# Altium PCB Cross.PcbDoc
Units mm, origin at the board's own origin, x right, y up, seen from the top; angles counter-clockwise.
Board outline 100 x 65 mm, 2 copper layers (Top Layer, Bottom Layer); 31 components, 20 nets, 115 pads, 5 vias.
Unrouted connection lines stored in the file: 4.
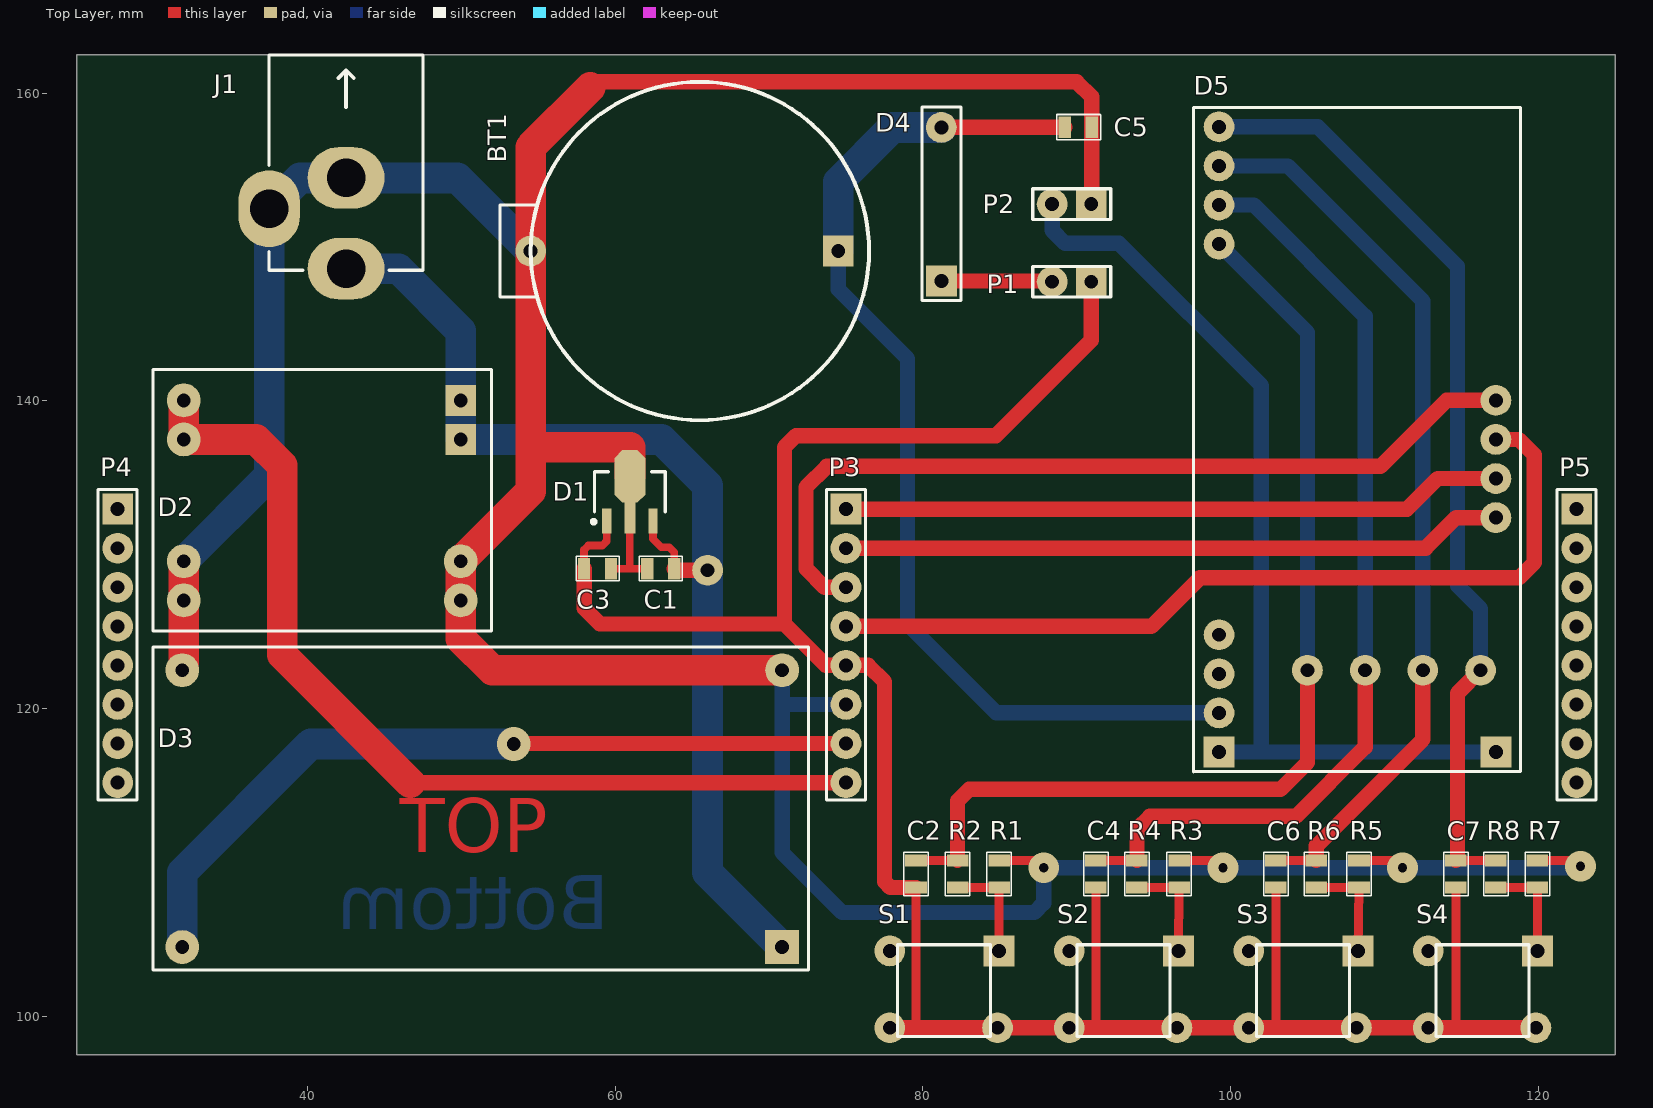
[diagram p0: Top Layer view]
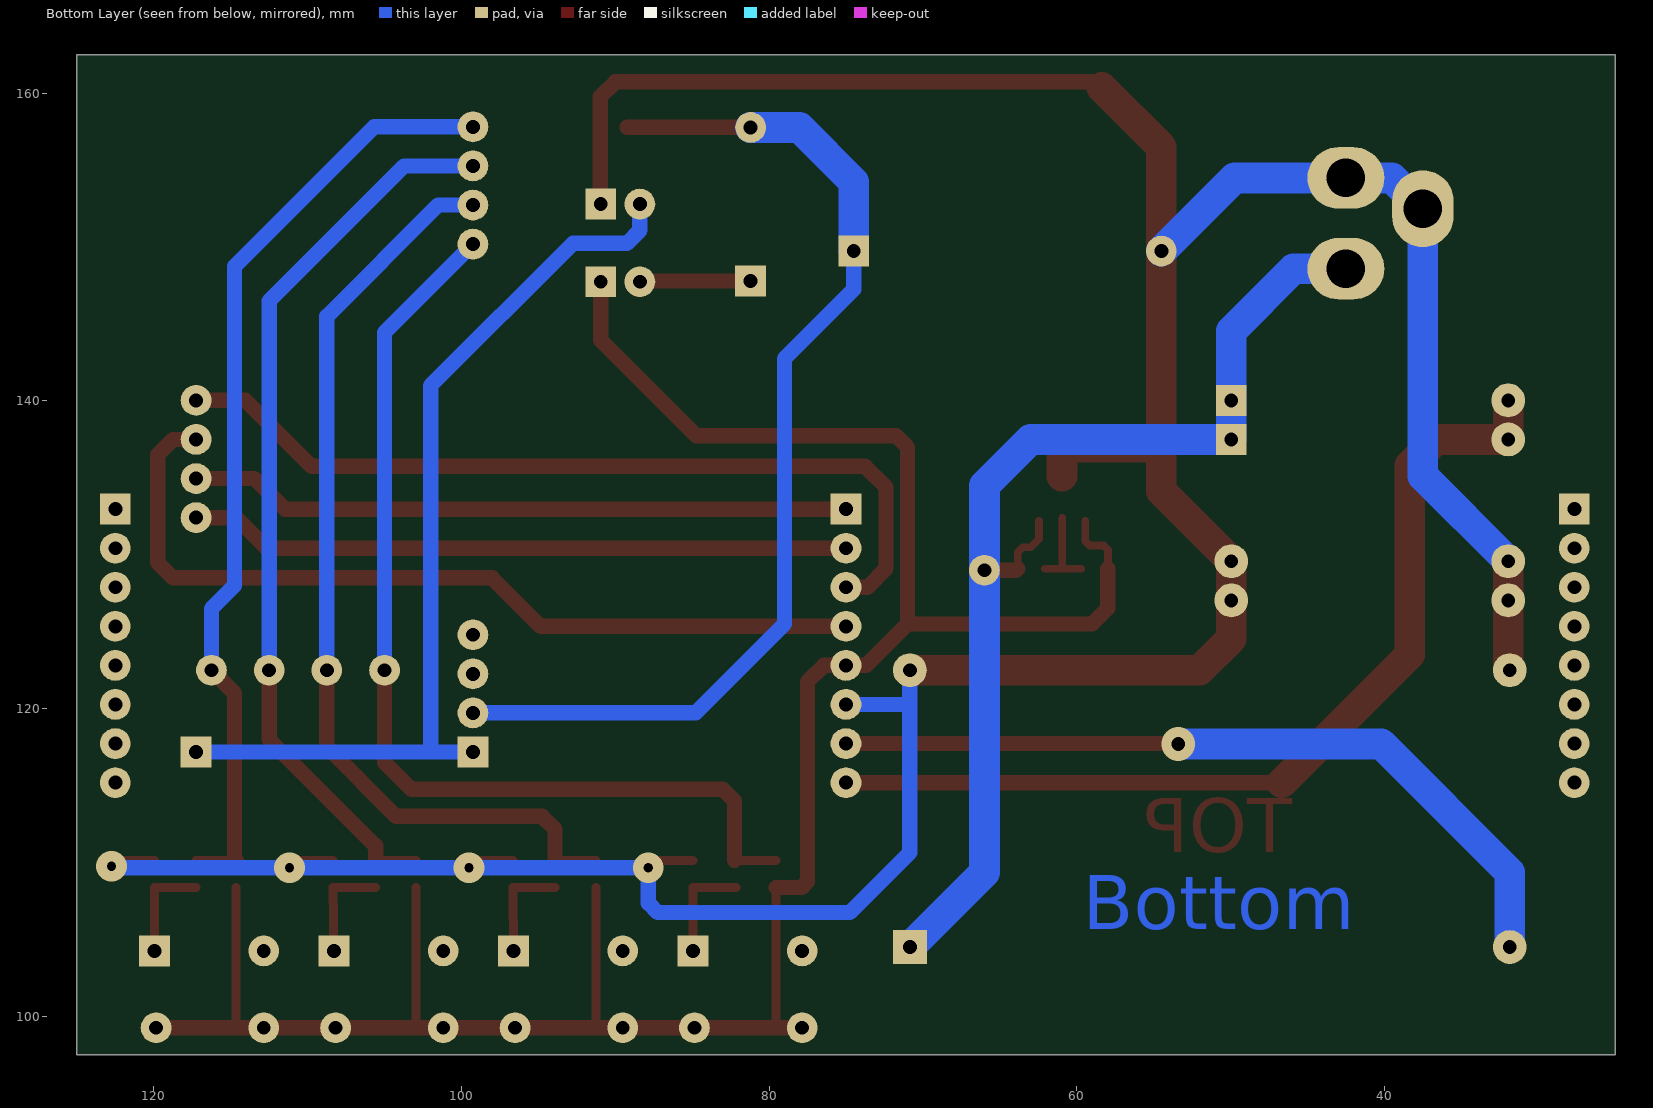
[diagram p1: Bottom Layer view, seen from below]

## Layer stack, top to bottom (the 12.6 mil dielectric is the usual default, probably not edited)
Top Solder: solder mask 0.0102, Solder Resist, Dk 3.5
Top Layer: signal copper 0.0356
Dielectric 1: dielectric 0.32, FR-4, Dk 4.8
Bottom Layer: signal copper 0.0356
Bottom Solder: solder mask 0.0102, Solder Resist, Dk 3.5

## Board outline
25,97.5 25,162.5 125,162.5 125,97.5

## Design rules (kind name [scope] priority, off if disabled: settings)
Clearance [All] p1: gap=0.4 ignorepadtopadclearanceinfootprint=FALSE except(0: Arc-Hole Track-Hole SMDPad-Hole THPad-Hole Via-Hole Fill-Hole Poly-Hole Region-Hole Text-Hole)
PolygonConnect [All] p1: connectstyle=Relief reliefconductorwidth=0.254 reliefentries=4 polygonreliefangle="90 Angle" airgapwidth=0.254
RoutingVias [All] p1: holewidth=0.711 width=1.27 viastyle="Through Hole" minholewidth=0.711 minwidth=1.27 maxholewidth=0.711 maxwidth=1.27
SolderMaskExpansion [All] p1: expansion=0.102
Width [All] p1: maxlimit=2 minlimit=0.2 preferedwidth=1 minimp=50.000000 maximp=50.000000 favimp=50.000000
30 further rules are at their usual default settings.

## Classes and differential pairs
component class Cross: BT1 C1 C2 C3 C4 C5 C6 C7 D1 D2 D3 D4 D5 J1 P1 P2 P3 R1 R2 R3 R4 R5 R6 R7 R8 S1 S2 S3 S4

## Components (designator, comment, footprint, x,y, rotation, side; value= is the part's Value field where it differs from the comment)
BT1 "Battery" VBAT 74.5,149.75 r180 top
C1 "Capacitor" C0805 62.95,129.1 r0 top
C2 "Capacitor" C0805 79.55,109.25 r270 top
C3 "Capacitor" C0805 58.85,129.1 r180 top
C4 "Capacitor" C0805 91.25,109.25 r270 top
C5 "Capacitor" C0805 90.1,157.8 r180 top
C6 "Capacitor" C0805 102.95,109.25 r270 top
C7 "Capacitor" C0805 114.65,109.25 r270 top
D1 "78L03" SOT89M 60.95,134.1 r90 top
D2 "DC-DC_1.5V" DC-DC_1.5V 29.95,140.04 r0 top
D3 "DC-DC_30V" DC-DC_30V 71.85,104.5 r180 top
D4 "Diode 1N914" Diode 81.2,147.8 r90 top
D5 "STM32F103C8T6" STM32F103C8T6_13pins 99.25,117.18 r90 top
J1 "PWR2.5" KLD-0202 42.5,162.5 r270 top
P1 "Header 2" 2pin 90.94,147.75 r180 top
P2 "Header 2" 2pin 90.94,152.8 r180 top
P3 "8pin" 8PIN 75,132.97 r270 top
P4 "8pin" 8PIN 27.65,132.97 r270 top (schematic designator P3)
P5 "8pin" 8PIN 122.5,132.97 r270 top (schematic designator P3)
R1 "Rezistor" C0805 84.95,109.25 r270 top
R2 "Rezistor" C0805 82.25,109.25 r90 top
R3 "Rezistor" C0805 96.65,109.25 r270 top
R4 "Rezistor" C0805 93.917,109.25 r90 top
R5 "Rezistor" C0805 108.35,109.25 r270 top
R6 "Rezistor" C0805 105.583,109.25 r90 top
R7 "Rezistor" C0805 119.95,109.25 r270 top
R8 "Rezistor" C0805 117.25,109.25 r90 top
S1 "SW-DPST" DPST-4 81.85,100.25 r270 top
S2 "SW-DPST" DPST-4 93.517,100.25 r270 top
S3 "SW-DPST" DPST-4 105.183,100.25 r270 top
S4 "SW-DPST" DPST-4 116.85,100.25 r270 top

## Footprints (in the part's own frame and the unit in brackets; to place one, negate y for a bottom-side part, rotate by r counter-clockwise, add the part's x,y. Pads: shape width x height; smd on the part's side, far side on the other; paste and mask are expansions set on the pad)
2pin [mm] "Connector; Header; 4 Position"
  rect 2x2 hole 0.9: 1(0,0)
  round 2 hole 0.9: 2(2.54,0)
  silkscreen extent -1.27,-1 3.8,1
8PIN [mm] "Connector; Header; 4 Position"
  rect 2x2 hole 0.9: 1(0,0)
  round 2 hole 0.9: 2(2.54,0) 3(5.08,0) 4(7.62,0) 5(10.16,0) 6(12.7,0) 7(15.24,0) 8(17.78,0)
  silkscreen extent -1.27,-1.27 18.9,1.27
C0805 [mm] "Chip Capacitor, Body 2.0x1.3mm, IPC High Density"
  rect 0.8x1.4 smd: 1(-0.877,0) 2(0.877,0)
  silkscreen extent -1.4,-0.8 1.4,0.8, body extent -1.1,-0.72 1.1,0.72, height 1.4
DC-DC_1.5V [mm] "Connector; Header; 2 Position"
  rect 2x2 hole 0.9: 1(20,-2.54) 1(20,0)
  round 2.2 hole 0.9: 2(2,-2.54) 2(2,0) 3(2,-13) 3(2,-10.46) 4(20,-13) 4(20,-10.46)
  silkscreen extent 0,-15 22,2
DC-DC_30V [mm] "Connector; Header; 17 Position"
  rect 2.2x2.2 hole 0.9: 1(1,0)
  round 2.2 hole 0.9: 2(40,0) 3(1,-18) 4(40,-18)
  silkscreen extent -0.7,-19.5 41.9,1.5
Diode [mm] "Connector; Header; 4 Position"
  rect 2x2 hole 0.9: 1(0,0)
  round 2 hole 0.9: 2(9.98,0)
  silkscreen extent -1.27,-1.27 11.3,1.27
DPST-4 [mm] "Switch; 4 Leads"
  rect 2x2 hole 0.9: 1(-4,3.1)
  round 2 hole 0.9: 2(1,3) 3(-4,-4) 4(1,-4)
  silkscreen extent -4.4,-3.5 1.56,2.54
KLD-0202 [mm] "DC Power Jack, 2.5mm, KLD Series, PCB Mount"
  oval 4x5 hole 2.5: 1(13.9,0) 3(8,0)
  oval 5x4 hole 2.5: 2(10,-5)
  silkscreen extent 0,-5 14,5
SOT89M [mm] "SOT89, 3-Leads, Body 4.5x2.4 mm, Pitch 1.5mm, Lead Span 4.1mm, IPC Low Density"
  rect 1.6x0.6 smd: 1(-1.9,1.5) 3(-1.9,-1.5)
  rect 2x0.7 smd: 2(-1.7,0)
  oct 3.4x2 smd: 2(1,0)
  silkscreen extent -2.07,-2.3 1.3,2.47, body extent -1.3,-2.3 1.3,2.3, height 1.6
STM32F103C8T6_13pins [mm] "Connector; Header; 17 Position"
  rect 2x2 hole 0.9: 1(0,0) 18(0,-18)
  round 2 hole 0.9: 2(2.54,0) 3(5.08,0) 4(7.62,0) 14(33.02,0) 15(35.56,0) 16(38.1,0) 17(40.64,0) 24(15.24,-18) 25(17.78,-18) 26(20.32,-18) 27(22.86,-18)
  silkscreen extent -1.3,-19.6 41.91,1.67
VBAT [mm] "Connector; Header; 4 Position"
  rect 2x2 hole 0.9: 1(0,0)
  round 2 hole 0.9: 2(20,0)
  silkscreen extent -2,-11 22,11

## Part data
BT1: "Multicell Battery"
D4: "High Conductance Fast Diode"
J1: "Low Voltage Power Supply Connector"
P1 P2: "Header, 2-Pin"
S1 S2 S3 S4: "Double-Pole, Single-Throw Switch"

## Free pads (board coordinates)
  round 2 hole 0.9: 5(66,129) 5(105,122.5) 5(108.75,122.5) 5(112.5,122.5) 5(116.25,122.5)

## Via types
v1: diameter 2, hole 0.6, Top Layer to Bottom Layer, 4 vias
v2: diameter 2.2, hole 0.9, Top Layer to Bottom Layer, 1 vias

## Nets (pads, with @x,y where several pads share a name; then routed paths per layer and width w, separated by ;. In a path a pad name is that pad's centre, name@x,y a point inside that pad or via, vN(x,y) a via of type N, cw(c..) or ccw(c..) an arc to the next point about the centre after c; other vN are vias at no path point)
3V3: C2.2 C3.2 C4.2 C6.2 C7.2 D1.1 P1.1 P3.5 S1.2 S1.4 S2.2 S2.4 S3.2 S3.4 S4.2 S4.4 | length 160.3
  Top Layer w0.5: C3.2 57.973,130.323 58.25,130.6 59.15,130.6 59.45,130.9 D1.1
  Top Layer w0.6: 79.45,99.25 79.55,99.35 C2.2 ; 91.05,99.25 91.25,99.45 C4.2 ; 102.95,99.25 C6.2 ; 114.65,99.25 C7.2
  Top Layer w1: C3.2 57.973,126.527 59,125.5 71,125.5 ; S1.4 79.45,99.25 S1.2 S2.4 91.05,99.25 S2.2 S3.4 102.95,99.25 S3.2 S4.4 114.65,99.25 S4.2 ; C2.2 77.877,108.373 77.5,108.75 77.5,121.75 76.44,122.81 P3.5 73.69,122.81 71,125.5 ; P1.1 90.94,143.94 84.75,137.75 71.75,137.75 71,137 71,125.5
30V: D3.2 P3.7 | length 51.5
  Top Layer w1: v2(53.4,117.7) 53.43,117.73 P3.7
  Bottom Layer w2: D3.2 31.85,109.35 40.2,117.7 v2(53.4,117.7)
Button1: C2.1 D5.14 pad.5@105,122.5 R2.2 | length 66.4
  Top Layer w0.6: C2.1 R2.2
  Top Layer w1: R2.2 82.25,114 83,114.75 103.25,114.75 105,116.5 pad.5@105,122.5
  Bottom Layer w1: D5.14 105,144.45 pad.5@105,122.5
Button2: C4.1 D5.15 pad.5@108.75,122.5 R4.2 | length 62.2
  Top Layer w0.6: C4.1 R4.2
  Top Layer w1: R4.2 93.917,112.167 94.75,113 104.25,113 108.75,117.5 pad.5@108.75,122.5
  Bottom Layer w1: D5.15 101.51,152.74 108.75,145.5 pad.5@108.75,122.5
Button3: C6.1 D5.16 pad.5@112.5,122.5 R6.2 | length 58.8
  Top Layer w0.6: C6.1 R6.2
  Top Layer w1: R6.2 105.583,111.083 112.5,118 pad.5@112.5,122.5
  Bottom Layer w1: D5.16 103.72,155.28 112.5,146.5 pad.5@112.5,122.5
Button4: C7.1 D5.17 pad.5@116.25,122.5 R8.2 | length 61.8
  Top Layer w0.6: C7.1 R8.2
  Top Layer w1: C7.1 114.75,110.227 114.75,121 pad.5@116.25,122.5
  Bottom Layer w1: D5.17 105.68,157.82 114.75,148.75 114.75,128 116.25,126.5 pad.5@116.25,122.5
CLK: D5.24 P3.2 | length 43.1
  Top Layer w1: P3.2 112.68,130.43 114.67,132.42 D5.24
DS: D5.25 P3.1 | length 43.1
  Top Layer w1: P3.1 111.47,132.97 113.46,134.96 D5.25
Glow1: D2.2 P3.8 | length 62
  Top Layer w1: 46.675,115.175 46.69,115.19 P3.8
  Top Layer w2: D2.2@31.95,140.04 31.95,137.5 36.65,137.5 38.35,135.8 38.35,123.5 46.675,115.175
GND: BT1.2 C1.1 C3.1 C5.1 D1.2 D2.3 D2.4 D3.3 D3.4 J1.2 J1.3 P2.1 P3.6 R1.1 R3.1 R5.1 R7.1 | length 251.3
  Top Layer w0.5: C3.1 60.95,129.1 ; D1.2@60.95,132.4 60.95,129.1 ; C1.1 60.95,129.1 ; v1@122.373,110.127 v1(122.75,109.75)
  Top Layer w0.6: R1.1 87.373,110.127 v1(87.85,109.65) ; R3.1 99.04,110.127 v1(99.517,109.65) ; R5.1 110.706,110.127 v1(111.183,109.65) ; R7.1 v1@122.373,110.127
  Top Layer w1: 58.375,160.375 58.75,160.75 90,160.75 90.977,159.773 C5.1 90.977,152.987 P2.1@90.79,152.8
  Top Layer w2: D3.4@31.95,123 31.95,127.04 D2.3@31.95,129.58 ; 58.375,160.375 54.5,156.5 BT1.2 54.5,136.9 ; D1.2@60.95,135.1 60.95,137 54.6,137 54.5,136.9 ; D3.3 52,122.5 49.95,124.55 49.95,127.04 49.95,129.58 54.5,134.13 54.5,136.9
  Bottom Layer w1: D3.3 70.85,120 ; P3.6 71.12,120.27 70.85,120 ; v1(122.75,109.75) 122.65,109.65 v1(111.183,109.65) v1(99.517,109.65) v1(87.85,109.65) 87.85,107.35 87.25,106.75 74.75,106.75 70.85,110.65 70.85,120
  Bottom Layer w2: D2.3@31.95,129.58 37.5,135.13 J1.2 39.5,154.5 J1.3 49.75,154.5 BT1.2
Lath: D5.26 P3.4 | length 56.4
  Top Layer w1: P3.4 94.85,125.35 98,128.5 118.75,128.5 119.75,129.5 119.75,136.5 118.75,137.5 D5.26
NetBT1_1: BT1.1 C5.2 D4.2 D5.2 | length 69.5
  Top Layer w1: D4.2 81.22,157.8 C5.2
  Bottom Layer w1: BT1.1 74.5,147.25 79,142.75 79,125.5 84.78,119.72 D5.2
  Bottom Layer w2: BT1.1 74.5,154.25 78.03,157.78 D4.2
NetD4_1: D4.1 P1.2 | length 7.2
  Top Layer w1: D4.1 88.35,147.8 P1.2
NetD5_1: D5.1 D5.18 P2.2 | length 61.3
  Bottom Layer w1: P2.2 88.4,151.1 89.25,150.25 92.75,150.25 102,141 102,117.18 ; D5.1 102,117.18 ; D5.18 102,117.18
NetR1_2: R1.2 R2.1 S1.1 S1.3 | length 6.8
  Top Layer w0.6: R2.1@82.15,108.373 R2.1 R1.2@84.85,108.373 ; S1.1 R1.2
NetR3_2: R3.2 R4.1 S2.1 S2.3 | length 6.9
  Top Layer w0.6: R4.1 R3.2 S2.1
NetR5_2: R5.2 R6.1 S3.1 S3.3 | length 6.9
  Top Layer w0.6: R6.1 R5.2 S3.1
NetR7_2: R7.2 R8.1 S4.1 S4.3 | length 6.8
  Top Layer w0.6: R8.1 R7.2 S4.1
Reset: D5.27 P3.3 | length 55.6
  Top Layer w1: P3.3 73.61,127.89 72.4,129.1 72.4,134.4 73.75,135.75 109.75,135.75 114.04,140.04 D5.27
VCC: C1.2 D1.3 D2.1 D3.1 J1.1 pad.5@66,129 | length 71.7
  Top Layer w0.5: D1.3 62.45,131.05 63,130.5 63.5,130.5 63.827,130.173 C1.2
  Top Layer w1: C1.2 63.927,129 pad.5@66,129
  Bottom Layer w2: J1.1 45.9,148.6 49.95,144.55 49.95,140.04 49.95,137.5 63,137.5 66,134.5 66,129 66,109.35 D3.1
pads on no net: D5.3 D5.4 P4.1 P4.2 P4.3 P4.4 P4.5 P4.6 P4.7 P4.8 P5.1 P5.2 P5.3 P5.4 P5.5 P5.6 P5.7 P5.8

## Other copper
Top Layer:
  text "TOP" at 46,109.5 h6
Bottom Layer:
  text "Bottom" at 59.6,104.5 h6

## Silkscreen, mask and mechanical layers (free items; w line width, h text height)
Mechanical 1:
  the board outline again, w0.2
